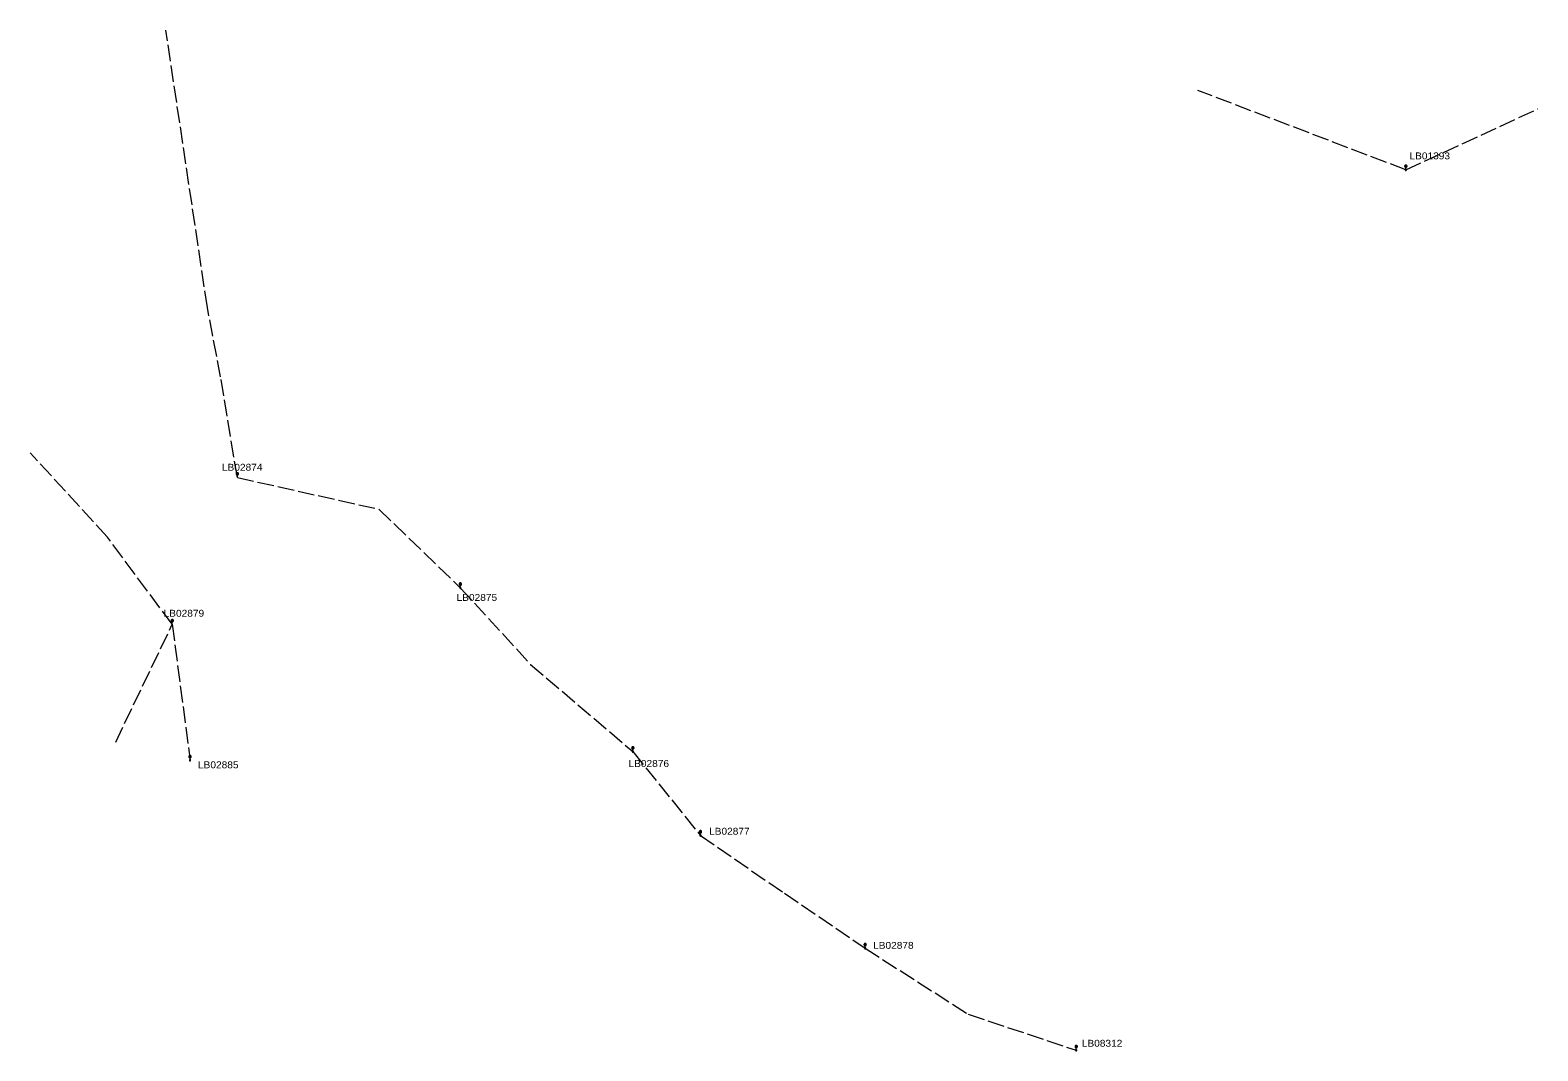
# Model space of a CAD drawing. Extents: x -692287 to -691812, y -971175 to -970853.
import ezdxf

# ---------------------------------------------------------------- set-up
doc = ezdxf.new("R2010")
doc.units = 0
doc.header["$LTSCALE"] = 0.87
doc.linetypes.add('LONG_DASHED', pattern=[7.5, 6, -1.5])
doc.layers.add('1', color=7, linetype='Continuous', lineweight=13)

msp = doc.modelspace()

# ---------------------------------------------------------------- linework, layer by layer
at = {"layer": '1', "linetype": 'LONG_DASHED'}
for p, q in [((-691853.74, -970897.36), (-691919.226, -970872.341)), ((-691853.74, -970897.36), (-691812.19, -970878.15)), ((-692259.82, -971077.48), (-692242, -971040.38)), ((-692242, -971040.38), (-692236.423, -971083.179))]:
    msp.add_line(p, q, dxfattribs=at)
at = {"layer": '1'}
for p, q in [((-691854.005, -970895.945), (-691853.475, -970896.475)), ((-691854.005, -970896.475), (-691853.475, -970895.945)), ((-691853.74, -970897.36), (-691853.74, -970896.585)), ((-692221.785, -970992.765), (-692221.255, -970993.295)), ((-692221.785, -970993.295), (-692221.255, -970992.765)), ((-692221.52, -970994.18), (-692221.52, -970993.405)), ((-692151.605, -971027.465), (-692151.075, -971027.995)), ((-692151.605, -971027.995), (-692151.075, -971027.465)), ((-692151.34, -971028.88), (-692151.34, -971028.105)), ((-692242.265, -971038.965), (-692241.735, -971039.495)), ((-692242.265, -971039.495), (-692241.735, -971038.965)), ((-692242, -971040.38), (-692242, -971039.605)), ((-692097.305, -971079.015), (-692096.775, -971079.545)), ((-692097.305, -971079.545), (-692096.775, -971079.015)), ((-692097.04, -971080.43), (-692097.04, -971079.655)), ((-692236.688, -971081.764), (-692236.158, -971082.294)), ((-692236.688, -971082.294), (-692236.158, -971081.764)), ((-692236.423, -971083.179), (-692236.423, -971082.404)), ((-692076.035, -971105.405), (-692075.505, -971105.935)), ((-692076.035, -971105.935), (-692075.505, -971105.405)), ((-692075.77, -971106.82), (-692075.77, -971106.045)), ((-692024.185, -971140.915), (-692023.655, -971141.445)), ((-692024.185, -971141.445), (-692023.655, -971140.915)), ((-692023.92, -971142.33), (-692023.92, -971141.555)), ((-691957.745, -971173.015), (-691957.215, -971173.545)), ((-691957.745, -971173.545), (-691957.215, -971173.015)), ((-691957.48, -971174.43), (-691957.48, -971173.655))]:
    msp.add_line(p, q, dxfattribs=at)
at = {"layer": '1', "linetype": 'LONG_DASHED'}
for points in [[(-692221.52, -970994.18), (-692226.79, -970962.51), (-692230.962, -970940.64), (-692244.01, -970853.39)], [(-692242, -971040.38), (-692262.44, -971012.95), (-692286.74, -970986.4)], [(-692221.52, -970994.18), (-692176.96, -971004.16), (-692151.34, -971028.88)], [(-692151.34, -971028.88), (-692129.24, -971053.01), (-692097.04, -971080.43), (-692075.77, -971106.82)], [(-692075.77, -971106.82), (-692049.32, -971125.02), (-692023.92, -971142.33)], [(-692023.92, -971142.33), (-691991.46, -971163.1), (-691957.48, -971174.43)]]:
    msp.add_lwpolyline(points, dxfattribs=at)
at = {"layer": '1'}
for points in [[(-691853.365, -970896.21), (-691853.371, -970896.145), (-691853.388, -970896.082), (-691853.415, -970896.022), (-691853.453, -970895.969), (-691853.499, -970895.923), (-691853.552, -970895.885), (-691853.612, -970895.858), (-691853.675, -970895.841), (-691853.74, -970895.835), (-691853.805, -970895.841), (-691853.868, -970895.858), (-691853.928, -970895.885), (-691853.981, -970895.923), (-691854.027, -970895.969), (-691854.065, -970896.022), (-691854.092, -970896.082), (-691854.109, -970896.145), (-691854.115, -970896.21), (-691854.109, -970896.275), (-691854.092, -970896.338), (-691854.065, -970896.398), (-691854.027, -970896.451), (-691853.981, -970896.497), (-691853.928, -970896.535), (-691853.868, -970896.562), (-691853.805, -970896.579), (-691853.74, -970896.585), (-691853.675, -970896.579), (-691853.612, -970896.562), (-691853.552, -970896.535), (-691853.499, -970896.497), (-691853.453, -970896.451), (-691853.415, -970896.398), (-691853.388, -970896.338), (-691853.371, -970896.275)], [(-691853.55, -970897.36), (-691853.553, -970897.327), (-691853.561, -970897.295), (-691853.575, -970897.265), (-691853.594, -970897.238), (-691853.618, -970897.214), (-691853.645, -970897.195), (-691853.675, -970897.181), (-691853.707, -970897.173), (-691853.74, -970897.17), (-691853.773, -970897.173), (-691853.805, -970897.181), (-691853.835, -970897.195), (-691853.862, -970897.214), (-691853.886, -970897.238), (-691853.905, -970897.265), (-691853.919, -970897.295), (-691853.927, -970897.327), (-691853.93, -970897.36), (-691853.927, -970897.393), (-691853.919, -970897.425), (-691853.905, -970897.455), (-691853.886, -970897.482), (-691853.862, -970897.506), (-691853.835, -970897.525), (-691853.805, -970897.539), (-691853.773, -970897.547), (-691853.74, -970897.55), (-691853.707, -970897.547), (-691853.675, -970897.539), (-691853.645, -970897.525), (-691853.618, -970897.506), (-691853.594, -970897.482), (-691853.575, -970897.455), (-691853.561, -970897.425), (-691853.553, -970897.393)], [(-691853.69, -970897.36), (-691853.691, -970897.351), (-691853.693, -970897.343), (-691853.697, -970897.335), (-691853.702, -970897.328), (-691853.708, -970897.322), (-691853.715, -970897.317), (-691853.723, -970897.313), (-691853.731, -970897.311), (-691853.74, -970897.31), (-691853.749, -970897.311), (-691853.757, -970897.313), (-691853.765, -970897.317), (-691853.772, -970897.322), (-691853.778, -970897.328), (-691853.783, -970897.335), (-691853.787, -970897.343), (-691853.789, -970897.351), (-691853.79, -970897.36), (-691853.789, -970897.369), (-691853.787, -970897.377), (-691853.783, -970897.385), (-691853.778, -970897.392), (-691853.772, -970897.398), (-691853.765, -970897.403), (-691853.757, -970897.407), (-691853.749, -970897.409), (-691853.74, -970897.41), (-691853.731, -970897.409), (-691853.723, -970897.407), (-691853.715, -970897.403), (-691853.708, -970897.398), (-691853.702, -970897.392), (-691853.697, -970897.385), (-691853.693, -970897.377), (-691853.691, -970897.369)], [(-692221.145, -970993.03), (-692221.151, -970992.965), (-692221.168, -970992.902), (-692221.195, -970992.842), (-692221.233, -970992.789), (-692221.279, -970992.743), (-692221.332, -970992.705), (-692221.392, -970992.678), (-692221.455, -970992.661), (-692221.52, -970992.655), (-692221.585, -970992.661), (-692221.648, -970992.678), (-692221.708, -970992.705), (-692221.761, -970992.743), (-692221.807, -970992.789), (-692221.845, -970992.842), (-692221.872, -970992.902), (-692221.889, -970992.965), (-692221.895, -970993.03), (-692221.889, -970993.095), (-692221.872, -970993.158), (-692221.845, -970993.218), (-692221.807, -970993.271), (-692221.761, -970993.317), (-692221.708, -970993.355), (-692221.648, -970993.382), (-692221.585, -970993.399), (-692221.52, -970993.405), (-692221.455, -970993.399), (-692221.392, -970993.382), (-692221.332, -970993.355), (-692221.279, -970993.317), (-692221.233, -970993.271), (-692221.195, -970993.218), (-692221.168, -970993.158), (-692221.151, -970993.095)], [(-692150.965, -971027.73), (-692150.971, -971027.665), (-692150.988, -971027.602), (-692151.015, -971027.542), (-692151.053, -971027.489), (-692151.099, -971027.443), (-692151.152, -971027.405), (-692151.212, -971027.378), (-692151.275, -971027.361), (-692151.34, -971027.355), (-692151.405, -971027.361), (-692151.468, -971027.378), (-692151.528, -971027.405), (-692151.581, -971027.443), (-692151.627, -971027.489), (-692151.665, -971027.542), (-692151.692, -971027.602), (-692151.709, -971027.665), (-692151.715, -971027.73), (-692151.709, -971027.795), (-692151.692, -971027.858), (-692151.665, -971027.918), (-692151.627, -971027.971), (-692151.581, -971028.017), (-692151.528, -971028.055), (-692151.468, -971028.082), (-692151.405, -971028.099), (-692151.34, -971028.105), (-692151.275, -971028.099), (-692151.212, -971028.082), (-692151.152, -971028.055), (-692151.099, -971028.017), (-692151.053, -971027.971), (-692151.015, -971027.918), (-692150.988, -971027.858), (-692150.971, -971027.795)], [(-692151.15, -971028.88), (-692151.153, -971028.847), (-692151.161, -971028.815), (-692151.175, -971028.785), (-692151.194, -971028.758), (-692151.218, -971028.734), (-692151.245, -971028.715), (-692151.275, -971028.701), (-692151.307, -971028.693), (-692151.34, -971028.69), (-692151.373, -971028.693), (-692151.405, -971028.701), (-692151.435, -971028.715), (-692151.462, -971028.734), (-692151.486, -971028.758), (-692151.505, -971028.785), (-692151.519, -971028.815), (-692151.527, -971028.847), (-692151.53, -971028.88), (-692151.527, -971028.913), (-692151.519, -971028.945), (-692151.505, -971028.975), (-692151.486, -971029.002), (-692151.462, -971029.026), (-692151.435, -971029.045), (-692151.405, -971029.059), (-692151.373, -971029.067), (-692151.34, -971029.07), (-692151.307, -971029.067), (-692151.275, -971029.059), (-692151.245, -971029.045), (-692151.218, -971029.026), (-692151.194, -971029.002), (-692151.175, -971028.975), (-692151.161, -971028.945), (-692151.153, -971028.913)], [(-692151.29, -971028.88), (-692151.291, -971028.871), (-692151.293, -971028.863), (-692151.297, -971028.855), (-692151.302, -971028.848), (-692151.308, -971028.842), (-692151.315, -971028.837), (-692151.323, -971028.833), (-692151.331, -971028.831), (-692151.34, -971028.83), (-692151.349, -971028.831), (-692151.357, -971028.833), (-692151.365, -971028.837), (-692151.372, -971028.842), (-692151.378, -971028.848), (-692151.383, -971028.855), (-692151.387, -971028.863), (-692151.389, -971028.871), (-692151.39, -971028.88), (-692151.389, -971028.889), (-692151.387, -971028.897), (-692151.383, -971028.905), (-692151.378, -971028.912), (-692151.372, -971028.918), (-692151.365, -971028.923), (-692151.357, -971028.927), (-692151.349, -971028.929), (-692151.34, -971028.93), (-692151.331, -971028.929), (-692151.323, -971028.927), (-692151.315, -971028.923), (-692151.308, -971028.918), (-692151.302, -971028.912), (-692151.297, -971028.905), (-692151.293, -971028.897), (-692151.291, -971028.889)], [(-692241.625, -971039.23), (-692241.631, -971039.165), (-692241.648, -971039.102), (-692241.675, -971039.042), (-692241.713, -971038.989), (-692241.759, -971038.943), (-692241.812, -971038.905), (-692241.872, -971038.878), (-692241.935, -971038.861), (-692242, -971038.855), (-692242.065, -971038.861), (-692242.128, -971038.878), (-692242.188, -971038.905), (-692242.241, -971038.943), (-692242.287, -971038.989), (-692242.325, -971039.042), (-692242.352, -971039.102), (-692242.369, -971039.165), (-692242.375, -971039.23), (-692242.369, -971039.295), (-692242.352, -971039.358), (-692242.325, -971039.418), (-692242.287, -971039.471), (-692242.241, -971039.517), (-692242.188, -971039.555), (-692242.128, -971039.582), (-692242.065, -971039.599), (-692242, -971039.605), (-692241.935, -971039.599), (-692241.872, -971039.582), (-692241.812, -971039.555), (-692241.759, -971039.517), (-692241.713, -971039.471), (-692241.675, -971039.418), (-692241.648, -971039.358), (-692241.631, -971039.295)], [(-692096.665, -971079.28), (-692096.671, -971079.215), (-692096.688, -971079.152), (-692096.715, -971079.092), (-692096.753, -971079.039), (-692096.799, -971078.993), (-692096.852, -971078.955), (-692096.912, -971078.928), (-692096.975, -971078.911), (-692097.04, -971078.905), (-692097.105, -971078.911), (-692097.168, -971078.928), (-692097.228, -971078.955), (-692097.281, -971078.993), (-692097.327, -971079.039), (-692097.365, -971079.092), (-692097.392, -971079.152), (-692097.409, -971079.215), (-692097.415, -971079.28), (-692097.409, -971079.345), (-692097.392, -971079.408), (-692097.365, -971079.468), (-692097.327, -971079.521), (-692097.281, -971079.567), (-692097.228, -971079.605), (-692097.168, -971079.632), (-692097.105, -971079.649), (-692097.04, -971079.655), (-692096.975, -971079.649), (-692096.912, -971079.632), (-692096.852, -971079.605), (-692096.799, -971079.567), (-692096.753, -971079.521), (-692096.715, -971079.468), (-692096.688, -971079.408), (-692096.671, -971079.345)], [(-692096.85, -971080.43), (-692096.853, -971080.397), (-692096.861, -971080.365), (-692096.875, -971080.335), (-692096.894, -971080.308), (-692096.918, -971080.284), (-692096.945, -971080.265), (-692096.975, -971080.251), (-692097.007, -971080.243), (-692097.04, -971080.24), (-692097.073, -971080.243), (-692097.105, -971080.251), (-692097.135, -971080.265), (-692097.162, -971080.284), (-692097.186, -971080.308), (-692097.205, -971080.335), (-692097.219, -971080.365), (-692097.227, -971080.397), (-692097.23, -971080.43), (-692097.227, -971080.463), (-692097.219, -971080.495), (-692097.205, -971080.525), (-692097.186, -971080.552), (-692097.162, -971080.576), (-692097.135, -971080.595), (-692097.105, -971080.609), (-692097.073, -971080.617), (-692097.04, -971080.62), (-692097.007, -971080.617), (-692096.975, -971080.609), (-692096.945, -971080.595), (-692096.918, -971080.576), (-692096.894, -971080.552), (-692096.875, -971080.525), (-692096.861, -971080.495), (-692096.853, -971080.463)], [(-692096.99, -971080.43), (-692096.991, -971080.421), (-692096.993, -971080.413), (-692096.997, -971080.405), (-692097.002, -971080.398), (-692097.008, -971080.392), (-692097.015, -971080.387), (-692097.023, -971080.383), (-692097.031, -971080.381), (-692097.04, -971080.38), (-692097.049, -971080.381), (-692097.057, -971080.383), (-692097.065, -971080.387), (-692097.072, -971080.392), (-692097.078, -971080.398), (-692097.083, -971080.405), (-692097.087, -971080.413), (-692097.089, -971080.421), (-692097.09, -971080.43), (-692097.089, -971080.439), (-692097.087, -971080.447), (-692097.083, -971080.455), (-692097.078, -971080.462), (-692097.072, -971080.468), (-692097.065, -971080.473), (-692097.057, -971080.477), (-692097.049, -971080.479), (-692097.04, -971080.48), (-692097.031, -971080.479), (-692097.023, -971080.477), (-692097.015, -971080.473), (-692097.008, -971080.468), (-692097.002, -971080.462), (-692096.997, -971080.455), (-692096.993, -971080.447), (-692096.991, -971080.439)], [(-692236.048, -971082.029), (-692236.053, -971081.964), (-692236.07, -971081.901), (-692236.098, -971081.842), (-692236.135, -971081.788), (-692236.182, -971081.742), (-692236.235, -971081.704), (-692236.294, -971081.677), (-692236.358, -971081.66), (-692236.423, -971081.654), (-692236.488, -971081.66), (-692236.551, -971081.677), (-692236.61, -971081.704), (-692236.664, -971081.742), (-692236.71, -971081.788), (-692236.747, -971081.842), (-692236.775, -971081.901), (-692236.792, -971081.964), (-692236.798, -971082.029), (-692236.792, -971082.094), (-692236.775, -971082.157), (-692236.747, -971082.217), (-692236.71, -971082.27), (-692236.664, -971082.316), (-692236.61, -971082.354), (-692236.551, -971082.382), (-692236.488, -971082.398), (-692236.423, -971082.404), (-692236.358, -971082.398), (-692236.294, -971082.382), (-692236.235, -971082.354), (-692236.182, -971082.316), (-692236.135, -971082.27), (-692236.098, -971082.217), (-692236.07, -971082.157), (-692236.053, -971082.094)], [(-692236.233, -971083.179), (-692236.236, -971083.146), (-692236.244, -971083.114), (-692236.258, -971083.084), (-692236.277, -971083.057), (-692236.301, -971083.034), (-692236.328, -971083.015), (-692236.358, -971083.001), (-692236.39, -971082.992), (-692236.423, -971082.989), (-692236.456, -971082.992), (-692236.488, -971083.001), (-692236.518, -971083.015), (-692236.545, -971083.034), (-692236.568, -971083.057), (-692236.587, -971083.084), (-692236.601, -971083.114), (-692236.61, -971083.146), (-692236.613, -971083.179), (-692236.61, -971083.212), (-692236.601, -971083.244), (-692236.587, -971083.274), (-692236.568, -971083.301), (-692236.545, -971083.325), (-692236.518, -971083.344), (-692236.488, -971083.358), (-692236.456, -971083.366), (-692236.423, -971083.369), (-692236.39, -971083.366), (-692236.358, -971083.358), (-692236.328, -971083.344), (-692236.301, -971083.325), (-692236.277, -971083.301), (-692236.258, -971083.274), (-692236.244, -971083.244), (-692236.236, -971083.212)], [(-692236.373, -971083.179), (-692236.373, -971083.17), (-692236.376, -971083.162), (-692236.379, -971083.154), (-692236.384, -971083.147), (-692236.391, -971083.141), (-692236.398, -971083.136), (-692236.406, -971083.132), (-692236.414, -971083.13), (-692236.423, -971083.129), (-692236.431, -971083.13), (-692236.44, -971083.132), (-692236.448, -971083.136), (-692236.455, -971083.141), (-692236.461, -971083.147), (-692236.466, -971083.154), (-692236.47, -971083.162), (-692236.472, -971083.17), (-692236.473, -971083.179), (-692236.472, -971083.188), (-692236.47, -971083.196), (-692236.466, -971083.204), (-692236.461, -971083.211), (-692236.455, -971083.217), (-692236.448, -971083.222), (-692236.44, -971083.226), (-692236.431, -971083.228), (-692236.423, -971083.229), (-692236.414, -971083.228), (-692236.406, -971083.226), (-692236.398, -971083.222), (-692236.391, -971083.217), (-692236.384, -971083.211), (-692236.379, -971083.204), (-692236.376, -971083.196), (-692236.373, -971083.188)], [(-692075.395, -971105.67), (-692075.401, -971105.605), (-692075.418, -971105.542), (-692075.445, -971105.482), (-692075.483, -971105.429), (-692075.529, -971105.383), (-692075.582, -971105.345), (-692075.642, -971105.318), (-692075.705, -971105.301), (-692075.77, -971105.295), (-692075.835, -971105.301), (-692075.898, -971105.318), (-692075.958, -971105.345), (-692076.011, -971105.383), (-692076.057, -971105.429), (-692076.095, -971105.482), (-692076.122, -971105.542), (-692076.139, -971105.605), (-692076.145, -971105.67), (-692076.139, -971105.735), (-692076.122, -971105.798), (-692076.095, -971105.858), (-692076.057, -971105.911), (-692076.011, -971105.957), (-692075.958, -971105.995), (-692075.898, -971106.022), (-692075.835, -971106.039), (-692075.77, -971106.045), (-692075.705, -971106.039), (-692075.642, -971106.022), (-692075.582, -971105.995), (-692075.529, -971105.957), (-692075.483, -971105.911), (-692075.445, -971105.858), (-692075.418, -971105.798), (-692075.401, -971105.735)], [(-692075.58, -971106.82), (-692075.583, -971106.787), (-692075.591, -971106.755), (-692075.605, -971106.725), (-692075.624, -971106.698), (-692075.648, -971106.674), (-692075.675, -971106.655), (-692075.705, -971106.641), (-692075.737, -971106.633), (-692075.77, -971106.63), (-692075.803, -971106.633), (-692075.835, -971106.641), (-692075.865, -971106.655), (-692075.892, -971106.674), (-692075.916, -971106.698), (-692075.935, -971106.725), (-692075.949, -971106.755), (-692075.957, -971106.787), (-692075.96, -971106.82), (-692075.957, -971106.853), (-692075.949, -971106.885), (-692075.935, -971106.915), (-692075.916, -971106.942), (-692075.892, -971106.966), (-692075.865, -971106.985), (-692075.835, -971106.999), (-692075.803, -971107.007), (-692075.77, -971107.01), (-692075.737, -971107.007), (-692075.705, -971106.999), (-692075.675, -971106.985), (-692075.648, -971106.966), (-692075.624, -971106.942), (-692075.605, -971106.915), (-692075.591, -971106.885), (-692075.583, -971106.853)], [(-692075.72, -971106.82), (-692075.721, -971106.811), (-692075.723, -971106.803), (-692075.727, -971106.795), (-692075.732, -971106.788), (-692075.738, -971106.782), (-692075.745, -971106.777), (-692075.753, -971106.773), (-692075.761, -971106.771), (-692075.77, -971106.77), (-692075.779, -971106.771), (-692075.787, -971106.773), (-692075.795, -971106.777), (-692075.802, -971106.782), (-692075.808, -971106.788), (-692075.813, -971106.795), (-692075.817, -971106.803), (-692075.819, -971106.811), (-692075.82, -971106.82), (-692075.819, -971106.829), (-692075.817, -971106.837), (-692075.813, -971106.845), (-692075.808, -971106.852), (-692075.802, -971106.858), (-692075.795, -971106.863), (-692075.787, -971106.867), (-692075.779, -971106.869), (-692075.77, -971106.87), (-692075.761, -971106.869), (-692075.753, -971106.867), (-692075.745, -971106.863), (-692075.738, -971106.858), (-692075.732, -971106.852), (-692075.727, -971106.845), (-692075.723, -971106.837), (-692075.721, -971106.829)], [(-692023.545, -971141.18), (-692023.551, -971141.115), (-692023.568, -971141.052), (-692023.595, -971140.992), (-692023.633, -971140.939), (-692023.679, -971140.893), (-692023.732, -971140.855), (-692023.792, -971140.828), (-692023.855, -971140.811), (-692023.92, -971140.805), (-692023.985, -971140.811), (-692024.048, -971140.828), (-692024.108, -971140.855), (-692024.161, -971140.893), (-692024.207, -971140.939), (-692024.245, -971140.992), (-692024.272, -971141.052), (-692024.289, -971141.115), (-692024.295, -971141.18), (-692024.289, -971141.245), (-692024.272, -971141.308), (-692024.245, -971141.368), (-692024.207, -971141.421), (-692024.161, -971141.467), (-692024.108, -971141.505), (-692024.048, -971141.532), (-692023.985, -971141.549), (-692023.92, -971141.555), (-692023.855, -971141.549), (-692023.792, -971141.532), (-692023.732, -971141.505), (-692023.679, -971141.467), (-692023.633, -971141.421), (-692023.595, -971141.368), (-692023.568, -971141.308), (-692023.551, -971141.245)], [(-692023.73, -971142.33), (-692023.733, -971142.297), (-692023.741, -971142.265), (-692023.755, -971142.235), (-692023.774, -971142.208), (-692023.798, -971142.184), (-692023.825, -971142.165), (-692023.855, -971142.151), (-692023.887, -971142.143), (-692023.92, -971142.14), (-692023.953, -971142.143), (-692023.985, -971142.151), (-692024.015, -971142.165), (-692024.042, -971142.184), (-692024.066, -971142.208), (-692024.085, -971142.235), (-692024.099, -971142.265), (-692024.107, -971142.297), (-692024.11, -971142.33), (-692024.107, -971142.363), (-692024.099, -971142.395), (-692024.085, -971142.425), (-692024.066, -971142.452), (-692024.042, -971142.476), (-692024.015, -971142.495), (-692023.985, -971142.509), (-692023.953, -971142.517), (-692023.92, -971142.52), (-692023.887, -971142.517), (-692023.855, -971142.509), (-692023.825, -971142.495), (-692023.798, -971142.476), (-692023.774, -971142.452), (-692023.755, -971142.425), (-692023.741, -971142.395), (-692023.733, -971142.363)], [(-692023.87, -971142.33), (-692023.871, -971142.321), (-692023.873, -971142.313), (-692023.877, -971142.305), (-692023.882, -971142.298), (-692023.888, -971142.292), (-692023.895, -971142.287), (-692023.903, -971142.283), (-692023.911, -971142.281), (-692023.92, -971142.28), (-692023.929, -971142.281), (-692023.937, -971142.283), (-692023.945, -971142.287), (-692023.952, -971142.292), (-692023.958, -971142.298), (-692023.963, -971142.305), (-692023.967, -971142.313), (-692023.969, -971142.321), (-692023.97, -971142.33), (-692023.969, -971142.339), (-692023.967, -971142.347), (-692023.963, -971142.355), (-692023.958, -971142.362), (-692023.952, -971142.368), (-692023.945, -971142.373), (-692023.937, -971142.377), (-692023.929, -971142.379), (-692023.92, -971142.38), (-692023.911, -971142.379), (-692023.903, -971142.377), (-692023.895, -971142.373), (-692023.888, -971142.368), (-692023.882, -971142.362), (-692023.877, -971142.355), (-692023.873, -971142.347), (-692023.871, -971142.339)], [(-691957.105, -971173.28), (-691957.111, -971173.215), (-691957.128, -971173.152), (-691957.155, -971173.092), (-691957.193, -971173.039), (-691957.239, -971172.993), (-691957.292, -971172.955), (-691957.352, -971172.928), (-691957.415, -971172.911), (-691957.48, -971172.905), (-691957.545, -971172.911), (-691957.608, -971172.928), (-691957.668, -971172.955), (-691957.721, -971172.993), (-691957.767, -971173.039), (-691957.805, -971173.092), (-691957.832, -971173.152), (-691957.849, -971173.215), (-691957.855, -971173.28), (-691957.849, -971173.345), (-691957.832, -971173.408), (-691957.805, -971173.468), (-691957.767, -971173.521), (-691957.721, -971173.567), (-691957.668, -971173.605), (-691957.608, -971173.632), (-691957.545, -971173.649), (-691957.48, -971173.655), (-691957.415, -971173.649), (-691957.352, -971173.632), (-691957.292, -971173.605), (-691957.239, -971173.567), (-691957.193, -971173.521), (-691957.155, -971173.468), (-691957.128, -971173.408), (-691957.111, -971173.345)], [(-691957.29, -971174.43), (-691957.293, -971174.397), (-691957.301, -971174.365), (-691957.315, -971174.335), (-691957.334, -971174.308), (-691957.358, -971174.284), (-691957.385, -971174.265), (-691957.415, -971174.251), (-691957.447, -971174.243), (-691957.48, -971174.24), (-691957.513, -971174.243), (-691957.545, -971174.251), (-691957.575, -971174.265), (-691957.602, -971174.284), (-691957.626, -971174.308), (-691957.645, -971174.335), (-691957.659, -971174.365), (-691957.667, -971174.397), (-691957.67, -971174.43), (-691957.667, -971174.463), (-691957.659, -971174.495), (-691957.645, -971174.525), (-691957.626, -971174.552), (-691957.602, -971174.576), (-691957.575, -971174.595), (-691957.545, -971174.609), (-691957.513, -971174.617), (-691957.48, -971174.62), (-691957.447, -971174.617), (-691957.415, -971174.609), (-691957.385, -971174.595), (-691957.358, -971174.576), (-691957.334, -971174.552), (-691957.315, -971174.525), (-691957.301, -971174.495), (-691957.293, -971174.463)], [(-691957.43, -971174.43), (-691957.431, -971174.421), (-691957.433, -971174.413), (-691957.437, -971174.405), (-691957.442, -971174.398), (-691957.448, -971174.392), (-691957.455, -971174.387), (-691957.463, -971174.383), (-691957.471, -971174.381), (-691957.48, -971174.38), (-691957.489, -971174.381), (-691957.497, -971174.383), (-691957.505, -971174.387), (-691957.512, -971174.392), (-691957.518, -971174.398), (-691957.523, -971174.405), (-691957.527, -971174.413), (-691957.529, -971174.421), (-691957.53, -971174.43), (-691957.529, -971174.439), (-691957.527, -971174.447), (-691957.523, -971174.455), (-691957.518, -971174.462), (-691957.512, -971174.468), (-691957.505, -971174.473), (-691957.497, -971174.477), (-691957.489, -971174.479), (-691957.48, -971174.48), (-691957.471, -971174.479), (-691957.463, -971174.477), (-691957.455, -971174.473), (-691957.448, -971174.468), (-691957.442, -971174.462), (-691957.437, -971174.455), (-691957.433, -971174.447), (-691957.431, -971174.439)]]:
    msp.add_lwpolyline(points, close=True, dxfattribs=at)

# ---------------------------------------------------------------- texts
at = {"layer": '1', "width": 1.1}
for s, p in [('LB01393', (-691852.602, -970894.04)), ('LB02874', (-692226.381, -970992.042)), ('LB02875', (-692152.524, -971033.009)), ('LB02879', (-692244.731, -971037.99)), ('LB02885', (-692233.911, -971085.689)), ('LB02876', (-692098.408, -971085.274)), ('LB02877', (-692073.047, -971106.592)), ('LB02878', (-692021.423, -971142.51)), ('LB08312', (-691955.732, -971173.322))]:
    msp.add_text(s, height=2.167, dxfattribs=at).set_placement(p)

doc.saveas('drawing.dxf')
